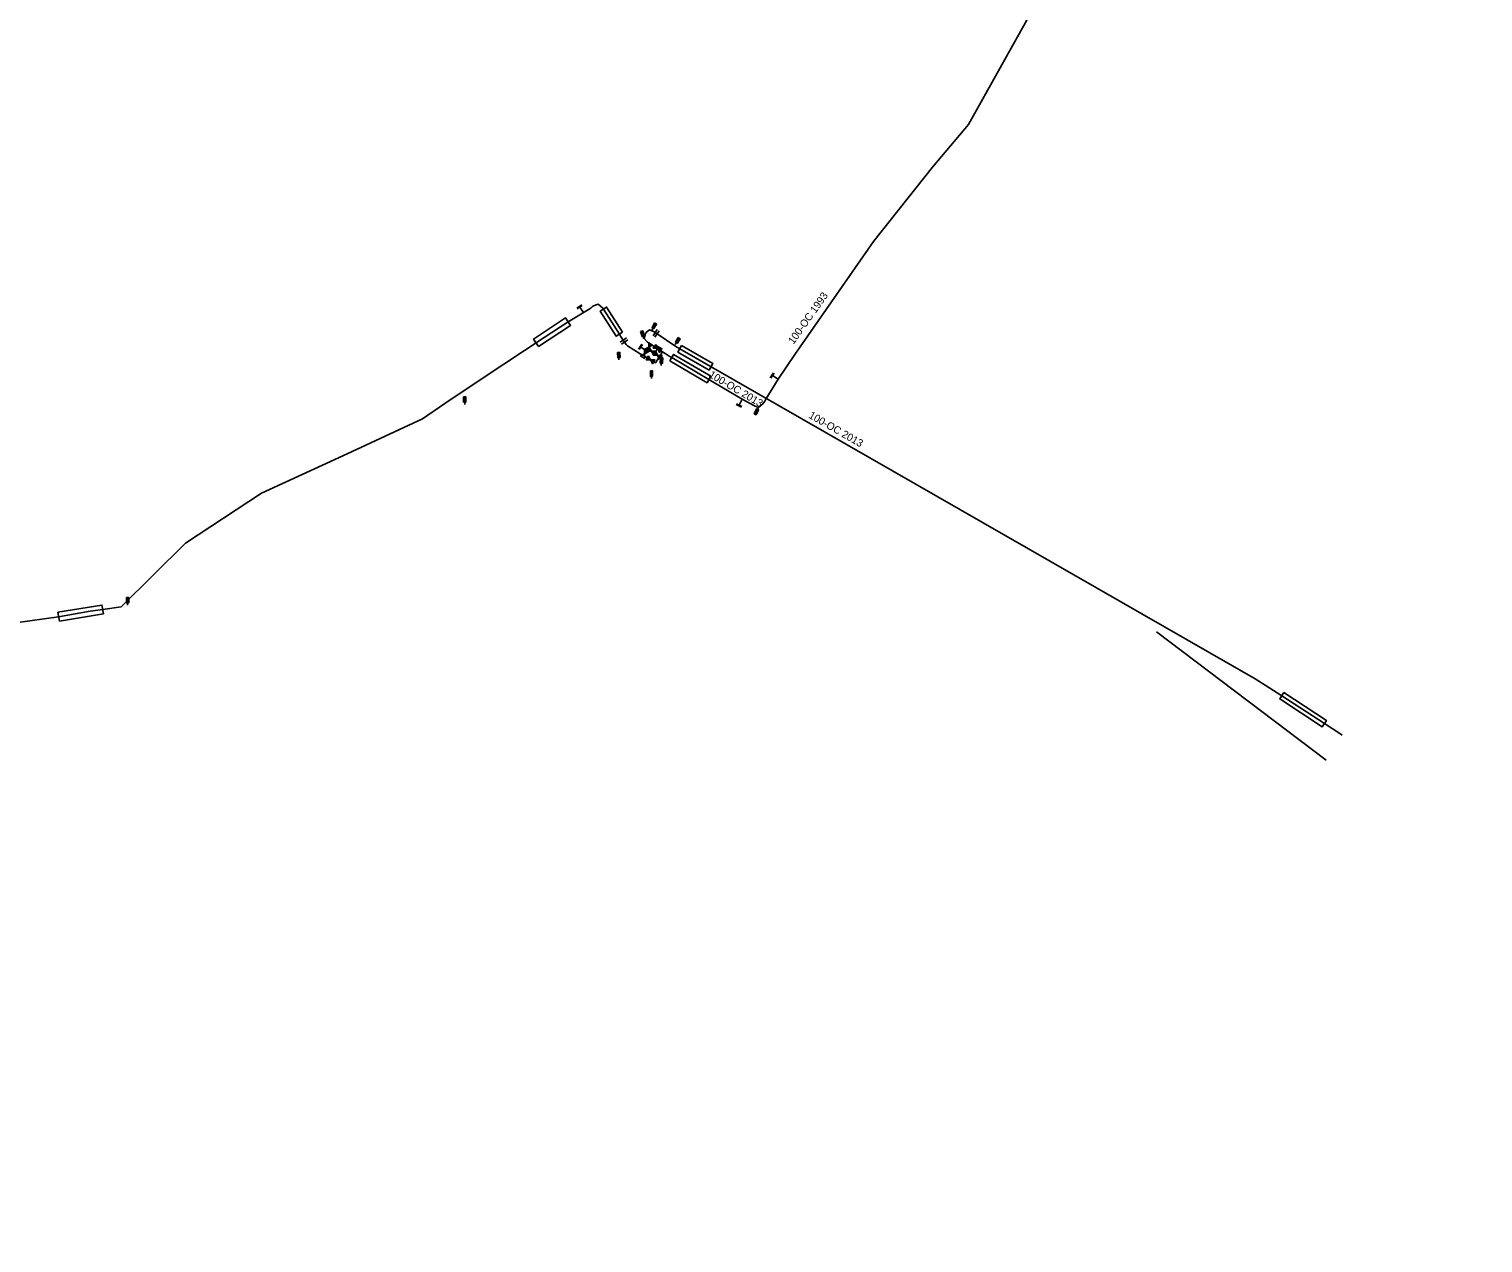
# Model space of a CAD drawing. Extents: x -737090 to -735731, y -1144778 to -1143369.
# Drawn here: x -735968.5 to -735775.4, y -1144013.9 to -1143852.6 of the extents above; entities that cross this region are included whole.
import ezdxf

# ---------------------------------------------------------------- set-up
doc = ezdxf.new("R2010")
doc.units = 0
for name, color, linetype in [('Vrstva 1', 7, 'Continuous'), ('Vrstva 2', 7, 'Continuous'), ('Vrstva 4', 7, 'Continuous'), ('Vrstva 9', 7, 'Continuous')]:
    doc.layers.add(name, color=color, linetype=linetype)

# ---------------------------------------------------------------- blocks, each defined once
blk = doc.blocks.new('DEC128')
at = {"layer": 'Vrstva 1'}
for p, q in [((-0.4, 1), (0.4, 1)), ((-0.4, 0.9), (0.4, 0.9)), ((0, 0), (0, 0.9))]:
    blk.add_line(p, q, dxfattribs=at)
blk = doc.blocks.new('DEC124')
at = {"layer": 'Vrstva 1'}
blk.add_lwpolyline([(-0.5, 0.3), (0.5, -0.3), (0.5, 0.3), (-0.5, -0.3), (-0.5, 0.3)], dxfattribs=at)
blk = doc.blocks.new('DEC125')
at = {"layer": 'Vrstva 1'}
for p, q in [((-0.15, 0.5), (-0.15, -0.5)), ((0.15, 0.5), (0.15, -0.5))]:
    blk.add_line(p, q, dxfattribs=at)
blk = doc.blocks.new('DEC129')
at = {"layer": 'Vrstva 1'}
blk.add_line((0, 1), (0, 0), dxfattribs=at)
blk.add_lwpolyline([(-0.15, 1), (0.15, 1), (0.15, 0.3), (-0.15, 0.3), (-0.15, 1)], dxfattribs=at)

msp = doc.modelspace()

# ---------------------------------------------------------------- linework, layer by layer
at = {"layer": 'Vrstva 1'}
for points in [[(-735786.84, -1143681.76), (-735790.34, -1143699.12), (-735793.68, -1143713.71), (-735794.71, -1143718.45), (-735784.15, -1143728.85), (-735775.35, -1143737.37), (-735783.12, -1143751.48), (-735792.88, -1143768.9), (-735800.29, -1143782.84), (-735808.19, -1143798.01), (-735814.09, -1143809.18), (-735821.48, -1143823.34), (-735827.74, -1143835.83), (-735836.12, -1143851.71), (-735843.7, -1143865.29), (-735848.47, -1143870.94), (-735856.31, -1143880.83), (-735866.79, -1143895.84), (-735868.99, -1143899.15), (-735870.61, -1143901.79)], [(-735886.9, -1143896), (-735887.32, -1143895.76), (-735889.02, -1143894.7), (-735889.19, -1143894.52), (-735889.48, -1143894.06), (-735889.92, -1143893.4), (-735890.08, -1143893.15), (-735892.22, -1143889.83), (-735892.35, -1143889.65), (-735892.9, -1143889.15), (-735893.51, -1143889.4), (-735893.66, -1143889.47), (-735893.86, -1143889.66), (-735894.1, -1143889.81)], [(-735894.1, -1143889.81), (-735896.9, -1143891.49), (-735900.09, -1143893.58), (-735908.04, -1143898.86), (-735913.29, -1143902.35), (-735916.25, -1143904.39), (-735926.83, -1143909.3), (-735937.62, -1143914.28), (-735947.73, -1143920.94), (-735956.29, -1143929.36), (-735958.74, -1143929.74), (-735960.42, -1143929.96), (-735964.6, -1143930.69), (-735972.22, -1143931.77), (-735977.91, -1143932.48), (-735984.24, -1143946.37), (-736005.74, -1143991.61), (-736017.15, -1144013.91), (-736037.01, -1144005.89), (-736064.19, -1143994.94), (-736110.43, -1143975.3), (-736137.12, -1143963.91), (-736169.03, -1143950.67)], [(-735885.95, -1143894.47), (-735886.35, -1143894.22), (-735886.78, -1143893.71), (-735886.6, -1143893.08), (-735886.47, -1143892.87), (-735886.08, -1143892.59), (-735885.57, -1143892.79), (-735885.21, -1143893.03), (-735882.58, -1143894.77), (-735882.07, -1143895.1), (-735877.91, -1143897.49), (-735805.59, -1143938.96), (-735803.78, -1143940.1), (-735802.08, -1143941.2), (-735796.42, -1143944.89), (-735794.36, -1143946.23), (-735794.05, -1143946.43)], [(-735886.75, -1143895.78), (-735886.49, -1143895.36), (-735886.35, -1143895.11)], [(-735886.35, -1143895.11), (-735886.2, -1143894.88)], [(-735885.86, -1143895.4), (-735886.35, -1143895.11)], [(-735886.2, -1143894.88), (-735885.95, -1143894.47)], [(-735885.01, -1143895.04), (-735885.95, -1143894.47)], [(-735884.34, -1143895.49), (-735885.01, -1143895.04)], [(-735886.9, -1143896), (-735886.75, -1143895.78)], [(-735885.96, -1143896.55), (-735886.9, -1143896)], [(-735884.78, -1143896.12), (-735885.28, -1143896.95), (-735885.96, -1143896.55)], [(-735885, -1143895.97), (-735885.86, -1143895.4)], [(-735884.78, -1143896.12), (-735885, -1143895.97)], [(-735884.34, -1143895.49), (-735884.78, -1143896.12)], [(-735870.61, -1143901.79), (-735870.77, -1143902.04), (-735870.99, -1143902.35), (-735871.61, -1143902.88), (-735872.15, -1143902.66), (-735873.76, -1143901.78), (-735878.19, -1143899.18), (-735883.13, -1143896.26), (-735883.46, -1143896.07), (-735884.02, -1143895.72), (-735884.34, -1143895.49)], [(-735818.73, -1143932.71), (-735796.16, -1143949.77)]]:
    msp.add_lwpolyline(points, dxfattribs=at)
at = {"layer": 'Vrstva 9'}
for points in [[(-735900.84, -1143894.8), (-735901.5, -1143893.8), (-735897.23, -1143890.99), (-735896.57, -1143891.99)], [(-735889.66, -1143892.88), (-735890.5, -1143893.42), (-735892.64, -1143890.1), (-735891.8, -1143889.56)], [(-735881.82, -1143894.67), (-735877.66, -1143897.06), (-735878.16, -1143897.92), (-735882.32, -1143895.53)], [(-735877.94, -1143898.75), (-735878.44, -1143899.61), (-735883.38, -1143896.69), (-735882.88, -1143895.83)], [(-735964.5, -1143931.28), (-735964.7, -1143930.1), (-735958.84, -1143929.15), (-735958.64, -1143930.33)], [(-735801.81, -1143940.78), (-735796.15, -1143944.47), (-735796.69, -1143945.31), (-735802.35, -1143941.62)]]:
    msp.add_lwpolyline(points, close=True, dxfattribs=at)

# ---------------------------------------------------------------- block references
at = {"layer": 'Vrstva 2'}
for p, rotation in [((-735886.75, -1143895.78), -121.63215229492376), ((-735886.2, -1143894.88), -123.47131806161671), ((-735885.86, -1143895.4), 150.28010590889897), ((-735885.01, -1143895.04), -33.256432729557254), ((-735885.96, -1143896.55), -31.915074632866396), ((-735885, -1143895.97), 146.78363709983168)]:
    msp.add_blockref('DEC124', p, dxfattribs=dict(at, rotation=rotation))
at = {"layer": 'Vrstva 4'}
for name, p, rotation in [('DEC128', (-735894.84, -1143890.29), 34.90346706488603), ('DEC129', (-735886.84, -1143893.72), 16.942232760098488), ('DEC129', (-735885.77, -1143892.6), -29.351583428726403), ('DEC125', (-735885.21, -1143893.03), -34.069237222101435), ('DEC125', (-735889.48, -1143894.06), -55.62607008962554), ('DEC128', (-735886.49, -1143895.36), 56.89831524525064), ('DEC128', (-735885.41, -1143895.7), -32.01479766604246), ('DEC129', (-735882.67, -1143894.53), -31.529479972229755), ('DEC129', (-735890.15, -1143896.57), 1.0298475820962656), ('DEC129', (-735884.52, -1143897.3), -3.227427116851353), ('DEC129', (-735885.82, -1143899.03), 0.3278180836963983), ('DEC128', (-735868.99, -1143899.15), 57.211936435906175), ('DEC129', (-735910.64, -1143902.48), -0.1305139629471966), ('DEC128', (-735873.76, -1143901.78), 152.8240375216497), ('DEC129', (-735871.61, -1143902.88), 154.46818978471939), ('DEC129', (-735955.44, -1143929.15), -0.016091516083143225)]:
    msp.add_blockref(name, p, dxfattribs=dict(at, rotation=rotation))

# ---------------------------------------------------------------- texts
at = {"layer": 'Vrstva 1'}
for s, rotation, p in [('100-OC 1993', 54.686, (-735866.95, -1143894.57)), ('100-OC 2013', 329.413, (-735878.3, -1143898.79)), ('100-OC 2013', 330.169, (-735865.03, -1143904.21))]:
    msp.add_text(s, height=1, rotation=rotation, dxfattribs=at).set_placement(p)

doc.saveas('drawing.dxf')
